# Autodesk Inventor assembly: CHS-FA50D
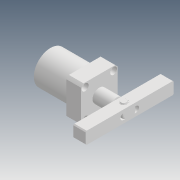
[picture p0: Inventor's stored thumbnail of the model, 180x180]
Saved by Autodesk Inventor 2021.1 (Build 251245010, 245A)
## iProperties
Created: 2019-04
Part Number: CHS-FA50D
Description: STEP AP203
Document SubType Name: Assembly
Designer: user
Title: chs-fa50d_asm.STEP
Revision Number: ÈÎºÎ
Sending System: SolidWorks 2017
Preprocessor: SwSTEP 2.0
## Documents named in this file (6)
- D:\Vault_2016\Projekty\Clamptek\Hydraulic\CHS\CHS-50\Inventor\CHS-FA50D\CHS-FA50D.iam
- D:\Vault_2016\Projekty\Clamptek\Hydraulic\CHS\CHS-50\Inventor\CHS-FA50D\CHS-FA50BT.ipt
- D:\Vault_2016\Projekty\Clamptek\Hydraulic\CHS\CHS-50\Inventor\CHS-FA50D\CHS-50DHSG_1.ipt
- D:\Vault_2016\Projekty\Clamptek\Hydraulic\CHS\CHS-50\Inventor\CHS-FA50D\CHS-50DYB_2.ipt
- D:\Vault_2016\Projekty\Clamptek\Hydraulic\CHS\CHS-50\Inventor\CHS-FA50D\Ïú.ipt
- D:\Vault_2016\Projekty\Clamptek\Hydraulic\CHS\CHS-50\Inventor\CHS-FA50D\ÖáÓÃµ²È¦.ipt
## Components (6 placed, 6 different names)
1. CHS-FA50BT_1
2. CHS-50DHSG_1_2
3. CHS-50DYB_2_3
4. Ïú_4
5. ÖáÓÃµ²È¦_5
6. ÖáÓÃµ²È¦_6
